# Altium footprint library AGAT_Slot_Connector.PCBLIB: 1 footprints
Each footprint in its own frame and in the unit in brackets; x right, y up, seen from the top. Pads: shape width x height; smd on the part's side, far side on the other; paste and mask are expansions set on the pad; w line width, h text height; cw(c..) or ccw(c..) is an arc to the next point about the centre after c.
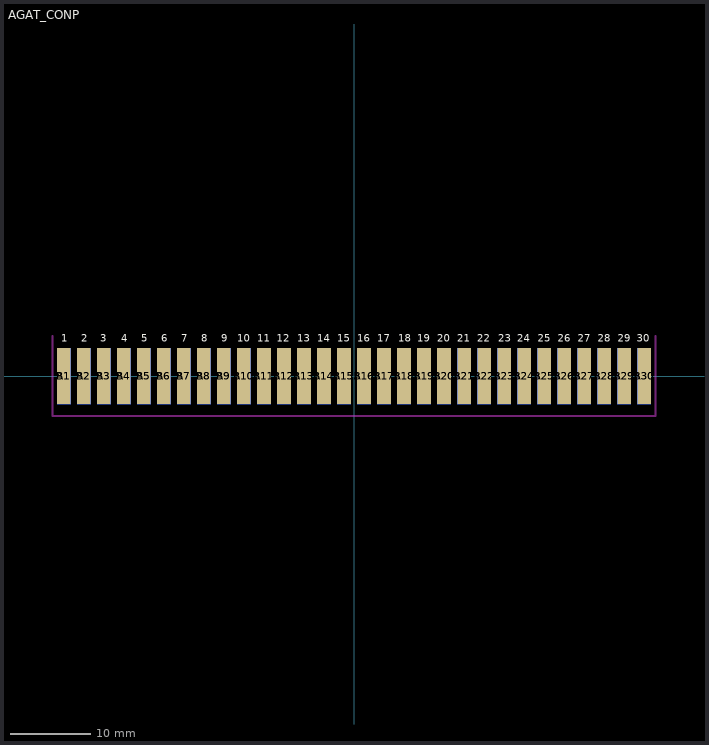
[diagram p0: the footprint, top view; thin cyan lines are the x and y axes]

## AGAT_CONP [mm]
pads (60):
  rect 1.7x7 smd far side: A1(-36.25,0) A2(-33.75,0) A3(-31.25,0) A4(-28.75,0) A5(-26.25,0) A6(-23.75,0) A7(-21.25,0) A8(-18.75,0) A9(-16.25,0) A10(-13.75,0) A11(-11.25,0) A12(-8.75,0) A13(-6.25,0) A14(-3.75,0) A15(-1.25,0) A16(1.25,0) A17(3.75,0) A18(6.25,0) A19(8.75,0) A20(11.25,0) A21(13.75,0) A22(16.25,0) A23(18.75,0) A24(21.25,0) A25(23.75,0) A26(26.25,0) A27(28.75,0) A28(31.25,0) A29(33.75,0) A30(36.25,0)
  rect 1.7x7 smd: B1(-36.25,0) B2(-33.75,0) B3(-31.25,0) B4(-28.75,0) B5(-26.25,0) B6(-23.75,0) B7(-21.25,0) B8(-18.75,0) B9(-16.25,0) B10(-13.75,0) B11(-11.25,0) B12(-8.75,0) B13(-6.25,0) B14(-3.75,0) B15(-1.25,0) B16(1.25,0) B17(3.75,0) B18(6.25,0) B19(8.75,0) B20(11.25,0) B21(13.75,0) B22(16.25,0) B23(18.75,0) B24(21.25,0) B25(23.75,0) B26(26.25,0) B27(28.75,0) B28(31.25,0) B29(33.75,0) B30(36.25,0)
Top Overlay:
  text "1" at -36.575,4 h1.55
  text "2" at -34.075,4 h1.55
  text "3" at -31.675,4 h1.55
  text "4" at -29.075,4 h1.55
  text "5" at -26.575,4 h1.55
  text "6" at -24.075,4 h1.55
  text "7" at -21.575,4 h1.55
  text "8" at -19.075,4 h1.55
  text "9" at -16.575,4 h1.55
  text "10" at -14.575,4 h1.55
  text "11" at -12.075,4 h1.55
  text "12" at -9.675,4 h1.55
  text "13" at -7.075,4 h1.55
  text "14" at -4.575,4 h1.55
  text "15" at -2.075,4 h1.55
  text "16" at 0.425,4 h1.55
  text "17" at 2.925,4 h1.55
  text "18" at 5.525,4 h1.55
  text "19" at 7.925,4 h1.55
  text "20" at 10.425,4 h1.55
  text "21" at 12.925,4 h1.55
  text "22" at 15.425,4 h1.55
  text "23" at 18.025,4 h1.55
  text "24" at 20.425,4 h1.55
  text "25" at 22.925,4 h1.55
  text "26" at 25.425,4 h1.55
  text "27" at 27.925,4 h1.55
  text "28" at 30.425,4 h1.55
  text "29" at 32.925,4 h1.55
  text "30" at 35.325,4 h1.55
Bottom Overlay:
  text "1" at -36.025,4 h1.55
  text "2" at -33.525,4 h1.55
  text "3" at -31.025,4 h1.55
  text "4" at -28.625,4 h1.55
  text "5" at -26.025,4 h1.55
  text "6" at -23.525,4 h1.55
  text "7" at -21.025,4 h1.55
  text "8" at -18.425,4 h1.55
  text "9" at -15.925,4 h1.55
  text "10" at -12.775,4 h1.55
  text "11" at -10.625,4 h1.55
  text "12" at -8.125,4 h1.55
  text "13" at -5.525,4 h1.55
  text "14" at -3.125,4 h1.55
  text "15" at -0.525,4 h1.55
  text "16" at 1.875,4 h1.55
  text "17" at 4.475,4 h1.55
  text "18" at 7.075,4 h1.55
  text "19" at 9.475,4 h1.55
  text "20" at 11.975,4 h1.55
  text "21" at 14.375,4 h1.55
  text "22" at 16.975,4 h1.55
  text "23" at 19.475,4 h1.55
  text "24" at 21.975,4 h1.55
  text "25" at 24.475,4 h1.55
  text "26" at 26.975,4 h1.55
  text "27" at 29.475,4 h1.55
  text "28" at 31.975,4 h1.55
  text "29" at 34.475,4 h1.55
  text "30" at 36.875,4 h1.55
Keep-Out Layer:
  lines w0.254: -37.65,5 -37.65,-5 37.65,-5 37.65,5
